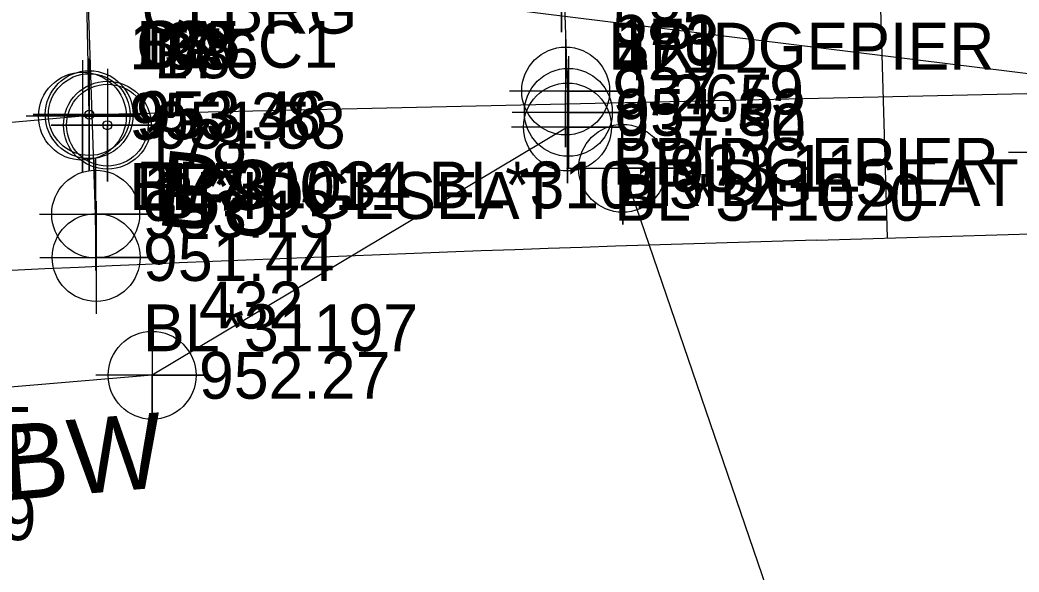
# Model space of a CAD drawing. Extents: x 1150279 to 1151282, y 654632 to 657999.
# Drawn here: x 1150713.8 to 1150767.1, y 657099.7 to 657129.2 of the extents above; entities that cross this region are included whole.
import ezdxf

# ---------------------------------------------------------------- set-up
doc = ezdxf.new("R2010")
doc.units = 0
for name, color, linetype in [('COGO Default Chain', 7, 'Continuous'), ('COGO Default Curve', 7, 'Continuous'), ('Cogo Default Point CELL', 7, 'Continuous'), ('COGO Default Point Elevation', 7, 'Continuous'), ('COGO Default Point Number', 7, 'Continuous'), ('Default Symbol CELL', 7, 'Continuous'), ('Default Symbol Cogo Comment', 7, 'Continuous'), ('Default Symbol Cogo Elevation', 7, 'Continuous'), ('Default Symbol Cogo Number', 7, 'Continuous'), ('Exist Horizontal Alignment', 7, 'Continuous'), ('Exist Hydro Jurisdictional Stream or Body of Water', 7, 'Continuous'), ('Exist Hydro Stream or Body of Water Cogo Elevation', 7, 'Continuous'), ('Exist Hydro Stream or Body of Water Cogo Number', 7, 'Continuous'), ('Exist Hydro Stream or Body of Water Cogo Point CELL', 7, 'Continuous'), ('Exist Other Culture Fence Line', 7, 'Continuous'), ('Exist Other Culture Fence Line Cogo Comment', 7, 'Continuous'), ('Exist Other Culture Fence Line Cogo Elevation', 7, 'Continuous'), ('Exist Other Culture Fence Line Cogo Number', 7, 'Continuous'), ('Exist Other Culture Fence Line Cogo Point CELL', 7, 'Continuous'), ('Exist Other Culture Fence Line Text', 7, 'Continuous'), ('Exist Other Culture Located Object CELL', 7, 'Continuous'), ('Exist Other Culture Located Object Text', 7, 'Continuous'), ('Exist Right of Way Line', 7, 'Continuous'), ('Exist Right of Way Width CELL', 7, 'Continuous'), ('Exist Roads EOP', 7, 'Continuous'), ('Exist Roads EOP Cogo Comment', 7, 'Continuous'), ('Exist Roads EOP Cogo Elevation', 7, 'Continuous'), ('Exist Roads EOP Cogo Number', 7, 'Continuous'), ('Exist Roads EOP Cogo Point CELL', 7, 'Continuous'), ('Exist Structure Major Bridge Seam', 7, 'Continuous'), ('Exist Structure Major Bridge Seam Cogo Comment', 7, 'Continuous'), ('Exist Structure Major Bridge Seam Cogo Elevation', 7, 'Continuous'), ('Exist Structure Major Bridge Seam Cogo Number', 7, 'Continuous'), ('Exist Structure Major Bridge Seam Cogo Point CELL', 7, 'Continuous'), ('Exist Structure Major Bridge WW', 7, 'Continuous'), ('Exist Structure Major Bridge WW Cogo Comment', 7, 'Continuous'), ('Exist Structure Major Bridge WW Cogo Elevation', 7, 'Continuous'), ('Exist Structure Major Bridge WW Cogo Number', 7, 'Continuous'), ('Exist Structure Major Bridge WW Cogo Point CELL', 7, 'Continuous'), ('Exist Structure Major Deck Tunnel Box Culvert', 7, 'Continuous'), ('Exist Structure Major Deck Tunnel Box Culvert Cogo Elevation', 7, 'Continuous'), ('Exist Structure Major Deck Tunnel Box Culvert Cogo Number', 7, 'Continuous'), ('Exist Structure Major Deck Tunnel Box Culvert Cogo Point CELL', 7, 'Continuous'), ('Exist Structure Minor Pipes CMP 15 Inch Cogo Comment', 7, 'Continuous')]:
    doc.layers.add(name, color=color, linetype=linetype)

msp = doc.modelspace()

# ---------------------------------------------------------------- linework, layer by layer
at = {"layer": 'COGO Default Chain'}
msp.add_line((1150614.756, 657145.261), (1150931.292, 657106.062), dxfattribs=at)
msp.add_arc((1150828.329, 654635.498), 2500, 91.662542, 95.877614, dxfattribs=at)
at = {"layer": 'COGO Default Curve'}
msp.add_arc((1150828.329, 654635.498), 2500, 91.662542, 95.877614, dxfattribs=at)
at = {"layer": 'Cogo Default Point CELL'}
for points in [[(1150717.448, 657127.141), (1150717.448, 657124.141)], [(1150718.416, 657126.579), (1150718.416, 657123.579)], [(1150714.448, 657124.141), (1150717.448, 657124.141)], [(1150717.448, 657124.141), (1150720.448, 657124.141)], [(1150717.448, 657124.141), (1150717.448, 657121.141)], [(1150715.416, 657123.579), (1150718.416, 657123.579)], [(1150718.416, 657123.579), (1150721.416, 657123.579)], [(1150718.416, 657123.579), (1150718.416, 657120.579)]]:
    msp.add_lwpolyline(points, dxfattribs=at)
for centre in [(1150717.448, 657124.141), (1150718.416, 657123.579)]:
    msp.add_circle(centre, 2.344, dxfattribs=at)
at = {"layer": 'Default Symbol CELL'}
for points in [[(1150742.655, 657134.545), (1150742.655, 657128.545), (1150742.655, 657131.545), (1150745.655, 657131.545), (1150739.655, 657131.545)], [(1150742.884, 657128.401), (1150742.884, 657122.401), (1150742.884, 657125.401), (1150745.884, 657125.401), (1150739.884, 657125.401)], [(1150743.027, 657127.263), (1150743.027, 657121.263), (1150743.027, 657124.263), (1150746.027, 657124.263), (1150740.027, 657124.263)], [(1150718.416, 657126.579), (1150718.416, 657120.579), (1150718.416, 657123.579), (1150721.416, 657123.579), (1150715.416, 657123.579)]]:
    msp.add_lwpolyline(points, dxfattribs=at)
for centre in [(1150742.884, 657125.401), (1150743.027, 657124.263), (1150718.416, 657123.579)]:
    msp.add_circle(centre, 2.344, dxfattribs=at)
at = {"layer": 'Exist Horizontal Alignment'}
msp.add_arc((1150828.329, 654635.498), 2500, 91.662542, 95.877614, dxfattribs=at)
at = {"layer": 'Exist Hydro Jurisdictional Stream or Body of Water'}
msp.add_lwpolyline([(1150745.794, 657124.778), (1150745.928, 657121.277), (1150758.485, 657084.636), (1150780.666, 657048.192), (1150800.517, 657025.21), (1150816.79, 656993.868)], dxfattribs=at)
at = {"layer": 'Exist Hydro Stream or Body of Water Cogo Point CELL'}
for points in [[(1150766.521, 657122.143), (1150772.521, 657122.143), (1150769.521, 657122.143), (1150769.521, 657119.143), (1150769.521, 657125.143)], [(1150742.928, 657121.277), (1150748.928, 657121.277), (1150745.928, 657121.277), (1150745.928, 657118.277), (1150745.928, 657124.277)]]:
    msp.add_lwpolyline(points, dxfattribs=at)
msp.add_circle((1150745.928, 657121.277), 2.344, dxfattribs=at)
at = {"layer": 'Exist Other Culture Fence Line'}
msp.add_lwpolyline([(1150742.984, 657123.479), (1150720.806, 657110.237), (1150694.904, 657108.057), (1150693.831, 657099.804)], dxfattribs=at)
at = {"layer": 'Exist Other Culture Fence Line Cogo Point CELL'}
for points in [[(1150742.984, 657126.479), (1150742.984, 657120.479), (1150742.984, 657123.479), (1150745.984, 657123.479), (1150739.984, 657123.479)], [(1150720.806, 657113.237), (1150720.806, 657107.237), (1150720.806, 657110.237), (1150723.806, 657110.237), (1150717.806, 657110.237)]]:
    msp.add_lwpolyline(points, dxfattribs=at)
for centre in [(1150742.984, 657123.479), (1150720.806, 657110.237)]:
    msp.add_circle(centre, 2.344, dxfattribs=at)
at = {"layer": 'Exist Other Culture Located Object CELL'}
for radius in [2.18, 0.24]:
    msp.add_circle((1150717.448, 657124.141), radius, dxfattribs=at)
at = {"layer": 'Exist Other Culture Located Object Text'}
for radius in [2.18, 0.24]:
    msp.add_circle((1150718.416, 657123.579), radius, dxfattribs=at)
at = {"layer": 'Exist Right of Way Line'}
msp.add_line((1150756.29, 657117.453), (1150788.111, 657118.377), dxfattribs=at)
msp.add_arc((1150828.329, 654635.498), 2483, 91.662542, 94.310193, dxfattribs=at)
at = {"layer": 'Exist Right of Way Width CELL'}
msp.add_line((1150760.069, 657117.563), (1150759.605, 657133.571), dxfattribs=at)
at = {"layer": 'Exist Roads EOP'}
msp.add_lwpolyline([(1150717.083, 657124.055), (1150672.367, 657120.059), (1150646.285, 657116.941)], dxfattribs=at)
at = {"layer": 'Exist Roads EOP Cogo Point CELL'}
msp.add_lwpolyline([(1150717.083, 657127.055), (1150717.083, 657121.055), (1150717.083, 657124.055), (1150720.083, 657124.055), (1150714.083, 657124.055)], dxfattribs=at)
msp.add_circle((1150717.083, 657124.055), 2.344, dxfattribs=at)
at = {"layer": 'Exist Structure Major Bridge Seam'}
msp.add_line((1150717.448, 657124.141), (1150717.083, 657143.072), dxfattribs=at)
at = {"layer": 'Exist Structure Major Bridge Seam Cogo Point CELL'}
msp.add_lwpolyline([(1150717.448, 657127.141), (1150717.448, 657121.141), (1150717.448, 657124.141), (1150720.448, 657124.141), (1150714.448, 657124.141)], dxfattribs=at)
msp.add_circle((1150717.448, 657124.141), 2.344, dxfattribs=at)
at = {"layer": 'Exist Structure Major Bridge WW'}
msp.add_lwpolyline([(1150717.82, 657116.521), (1150717.792, 657118.834), (1150716.802, 657148.017), (1150716.973, 657149.946)], dxfattribs=at)
at = {"layer": 'Exist Structure Major Bridge WW Cogo Point CELL'}
for points in [[(1150714.792, 657118.834), (1150720.792, 657118.834), (1150717.792, 657118.834), (1150717.792, 657121.834), (1150717.792, 657115.834)], [(1150714.82, 657116.521), (1150720.82, 657116.521), (1150717.82, 657116.521), (1150717.82, 657119.521), (1150717.82, 657113.521)]]:
    msp.add_lwpolyline(points, dxfattribs=at)
for centre in [(1150717.792, 657118.834), (1150717.82, 657116.521)]:
    msp.add_circle(centre, 2.344, dxfattribs=at)
at = {"layer": 'Exist Structure Major Deck Tunnel Box Culvert'}
msp.add_line((1150717.448, 657124.141), (1150798.272, 657125.958), dxfattribs=at)
msp.add_lwpolyline([(1150743.027, 657124.263), (1150742.363, 657144.022)], dxfattribs=at)
at = {"layer": 'Exist Structure Major Deck Tunnel Box Culvert Cogo Point CELL'}
msp.add_lwpolyline([(1150714.448, 657124.141), (1150720.448, 657124.141), (1150717.448, 657124.141), (1150717.448, 657127.141), (1150717.448, 657121.141)], dxfattribs=at)
msp.add_circle((1150717.448, 657124.141), 2.344, dxfattribs=at)

# ---------------------------------------------------------------- texts
at = {"layer": 'COGO Default Point Elevation'}
for s, p in [('953.46', (1150719.948, 657122.891)), ('951.53', (1150720.916, 657122.329))]:
    msp.add_text(s, height=2.5, dxfattribs=at).set_placement(p)
at = {"layer": 'COGO Default Point Number'}
for s, p in [('B3', (1150719.948, 657126.641)), ('B8', (1150720.916, 657126.079))]:
    msp.add_text(s, height=2.5, dxfattribs=at).set_placement(p)
at = {"layer": 'Default Symbol Cogo Comment'}
for s, p in [('CLBRG', (1150720.238, 657128.461)), ('BRIDGEPIER', (1150745.155, 657126.545)), ('BRIDGEPIER', (1150745.384, 657120.401)), ('BRIDGESEAT', (1150745.527, 657119.263)), ('BRIDGESEAT', (1150720.916, 657118.579))]:
    msp.add_text(s, height=2.5, dxfattribs=at).set_placement(p)
at = {"layer": 'Default Symbol Cogo Elevation'}
for s, p in [('937.79', (1150745.384, 657124.151)), ('951.32', (1150745.527, 657123.013)), ('951.53', (1150720.916, 657122.329))]:
    msp.add_text(s, height=2.5, dxfattribs=at).set_placement(p)
at = {"layer": 'Default Symbol Cogo Number'}
for s, p in [('585', (1150745.384, 657127.901)), ('173', (1150745.527, 657126.763)), ('176', (1150720.916, 657126.079))]:
    msp.add_text(s, height=2.5, dxfattribs=at).set_placement(p)
at = {"layer": 'Exist Hydro Stream or Body of Water Cogo Elevation'}
msp.add_text('933.11', height=2.5, dxfattribs=at).set_placement((1150748.428, 657120.027))
at = {"layer": 'Exist Hydro Stream or Body of Water Cogo Number'}
msp.add_text('265', height=2.5, dxfattribs=at).set_placement((1150748.428, 657123.777))
at = {"layer": 'Exist Other Culture Fence Line Cogo Comment'}
for s, p in [('BL*341020', (1150745.484, 657118.479)), ('EL*341028 EL*400519', (1150680.609, 657101.438))]:
    msp.add_text(s, height=2.5, dxfattribs=at).set_placement(p)
at = {"layer": 'Exist Other Culture Fence Line Cogo Elevation'}
for s, p in [('937.50', (1150745.484, 657122.229)), ('952.27', (1150723.306, 657108.987))]:
    msp.add_text(s, height=2.5, dxfattribs=at).set_placement(p)
at = {"layer": 'Exist Other Culture Fence Line Cogo Number'}
for s, p in [('429', (1150745.484, 657125.979)), ('432', (1150723.306, 657112.737))]:
    msp.add_text(s, height=2.5, dxfattribs=at).set_placement(p)
at = {"layer": 'Exist Other Culture Fence Line Text'}
msp.add_text('4SBW', height=4, rotation=4.8118, dxfattribs=at).set_placement((1150706.414, 657103.004))
at = {"layer": 'Exist Other Culture Located Object Text'}
msp.add_text('B8', height=4, rotation=353.6867, dxfattribs=at).set_placement((1150720.891, 657118.278))
at = {"layer": 'Exist Roads EOP Cogo Comment'}
msp.add_text('BL*30011', height=2.5, dxfattribs=at).set_placement((1150719.583, 657119.055))
at = {"layer": 'Exist Roads EOP Cogo Elevation'}
msp.add_text('953.38', height=2.5, dxfattribs=at).set_placement((1150719.583, 657122.805))
at = {"layer": 'Exist Roads EOP Cogo Number'}
msp.add_text('133', height=2.5, dxfattribs=at).set_placement((1150719.583, 657126.555))
at = {"layer": 'Exist Structure Major Bridge Seam Cogo Comment'}
msp.add_text('BL*31034 BL*31015', height=2.5, dxfattribs=at).set_placement((1150719.948, 657119.141))
at = {"layer": 'Exist Structure Major Bridge Seam Cogo Elevation'}
msp.add_text('953.46', height=2.5, dxfattribs=at).set_placement((1150719.948, 657122.891))
at = {"layer": 'Exist Structure Major Bridge Seam Cogo Number'}
msp.add_text('165', height=2.5, dxfattribs=at).set_placement((1150719.948, 657126.641))
at = {"layer": 'Exist Structure Major Bridge WW Cogo Comment'}
msp.add_text('BL*31197', height=2.5, dxfattribs=at).set_placement((1150720.32, 657111.521))
at = {"layer": 'Exist Structure Major Bridge WW Cogo Elevation'}
for s, p in [('953.13', (1150720.292, 657117.584)), ('951.44', (1150720.32, 657115.271))]:
    msp.add_text(s, height=2.5, dxfattribs=at).set_placement(p)
at = {"layer": 'Exist Structure Major Bridge WW Cogo Number'}
for s, p in [('178', (1150720.292, 657121.334)), ('177', (1150720.32, 657119.021))]:
    msp.add_text(s, height=2.5, dxfattribs=at).set_placement(p)
at = {"layer": 'Exist Structure Major Deck Tunnel Box Culvert Cogo Elevation'}
msp.add_text('953.46', height=2.5, dxfattribs=at).set_placement((1150719.948, 657122.891))
at = {"layer": 'Exist Structure Major Deck Tunnel Box Culvert Cogo Number'}
msp.add_text('CALC1', height=2.5, dxfattribs=at).set_placement((1150719.948, 657126.641))
at = {"layer": 'Exist Structure Minor Pipes CMP 15 Inch Cogo Comment'}
msp.add_text('BL*521525', height=2.5, dxfattribs=at).set_placement((1150697.911, 657106.053))

doc.saveas('drawing.dxf')
